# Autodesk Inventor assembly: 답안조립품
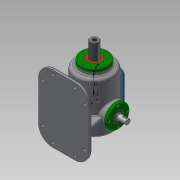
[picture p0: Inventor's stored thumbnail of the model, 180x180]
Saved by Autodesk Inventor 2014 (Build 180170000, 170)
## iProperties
Created: 2019-10
Part Number: 답안조립품
Document SubType Name: Assembly
Designer: NET
Author: NET
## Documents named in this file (17)
- C:\Users\net\Desktop\391004V1043\답안조립품.iam
- C:\Users\net\Desktop\391004V1043\본체.ipt
- C:\Users\net\Desktop\391004V1043\가변스프링.ipt
- C:\Users\net\Desktop\391004V1043\개스킷 A.ipt
- C:\Users\net\Desktop\391004V1043\개스킷 B.ipt
- C:\Users\net\Desktop\391004V1043\고정플레이트.ipt
- C:\Users\net\Desktop\391004V1043\베어링 6205.ipt
- 베어링 6205.ipt
- C:\Users\net\Desktop\391004V1043\볼트 M4x0.7.ipt
- C:\Users\net\Desktop\391004V1043\부시.ipt
- C:\Users\net\Desktop\391004V1043\상부커버.ipt
- C:\Users\net\Desktop\391004V1043\슬라이드 커버.ipt
- C:\Users\net\Desktop\391004V1043\슬라이드.ipt
- C:\Users\net\Desktop\391004V1043\오일 실 25 38 8.ipt
- C:\Users\net\Desktop\391004V1043\육각머리볼트 M4.ipt
- C:\Users\net\Desktop\391004V1043\축 커버.ipt
- C:\Users\net\Desktop\391004V1043\편심축.ipt
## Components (17 placed, 5 different names)
1. 가변스프링:1
2. 개스킷 A:1
3. 개스킷 B:1
4. 고정플레이트:1
5. 개스킷 B:2
6. M4x0.7:1
7. M4x0.7:4
8. M4x0.7:5
9. M4x0.7:6
10. M4x0.7:3
11. M4x0.7:7
12. M4x0.7:8
13. M4x0.7:9
14. M4x0.7:2
15. M4x0.7:10
16. M4x0.7:11
17. M4x0.7:12
